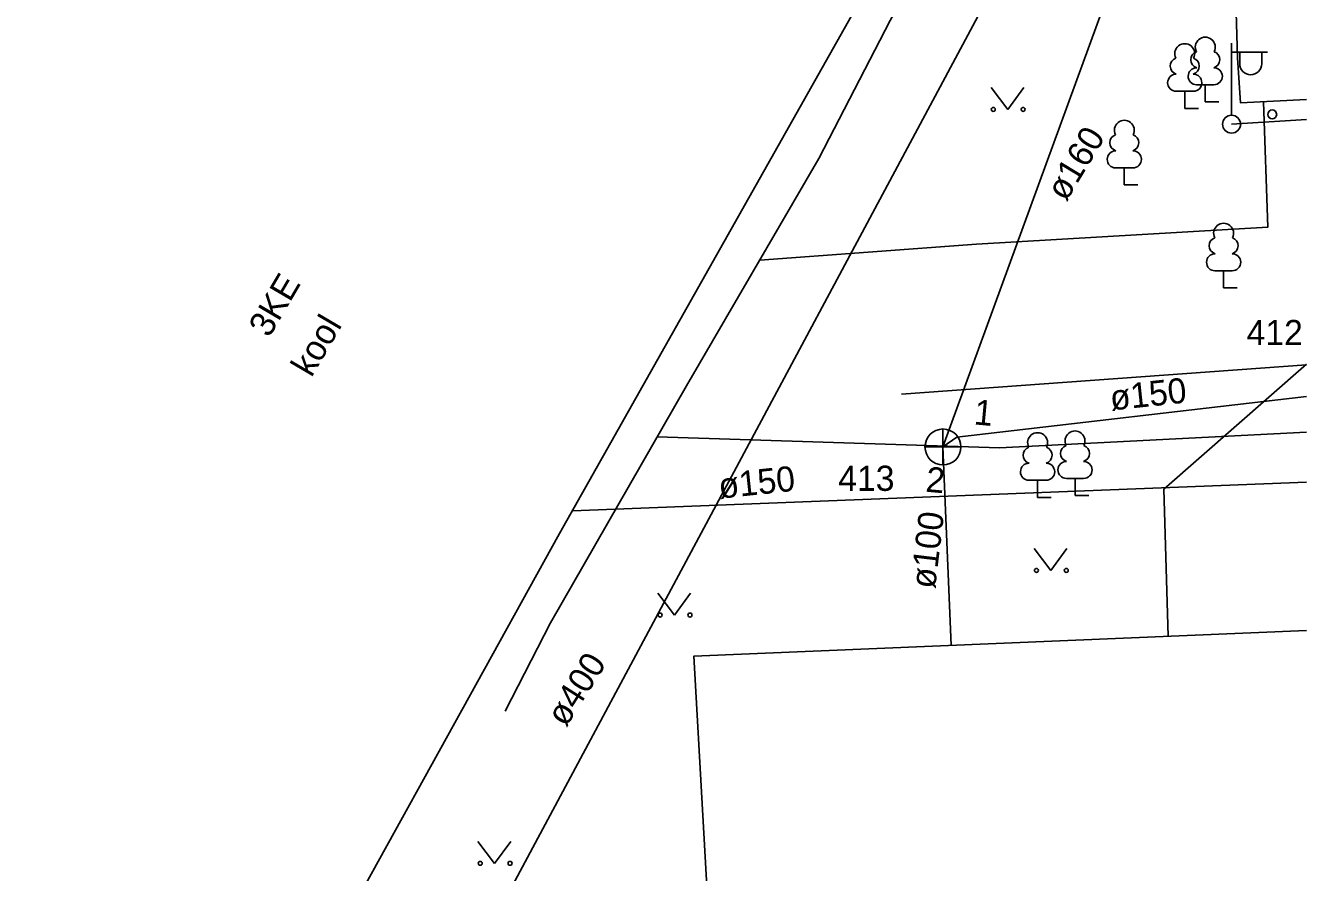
# Model space of a CAD drawing. Extents: x 713540 to 713867, y 6589774 to 6590061.
# Drawn here: x 713831.07 to 713866.67, y 6589884.71 to 6589908.24 of the extents above; entities that cross this region are included whole.
import ezdxf

# ---------------------------------------------------------------- set-up
doc = ezdxf.new("R2010")
doc.units = 0
for name, color, linetype in [('AED', 7, 'Continuous'), ('HALJASTUS', 7, 'Continuous'), ('HOONE', 7, 'Continuous'), ('HOONEDET', 7, 'Continuous'), ('KKAEV', 7, 'Continuous'), ('KORGUS', 7, 'Continuous'), ('KTRASS', 7, 'Continuous'), ('MPKAABEL', 7, 'Continuous'), ('POST', 7, 'Continuous'), ('PUU', 7, 'Continuous'), ('SIKAEV', 7, 'Continuous'), ('SKTRASS', 7, 'Continuous'), ('TEE', 7, 'Continuous'), ('TORU NR', 7, 'Continuous'), ('TTRASS', 7, 'Continuous'), ('VTRASS', 7, 'Continuous')]:
    doc.layers.add(name, color=color, linetype=linetype)

msp = doc.modelspace()

# ---------------------------------------------------------------- linework, layer by layer
at = {"layer": 'AED'}
msp.add_lwpolyline([(713866.671, 6589912.481), (713864.61, 6589912.43), (713864.76, 6589907.34)], dxfattribs=at)
at = {"layer": 'HALJASTUS'}
for p, q in [((713857.907, 6589906.517), (713858.37, 6589905.91)), ((713858.37, 6589905.91), (713858.816, 6589906.517)), ((713859.107, 6589893.707), (713859.57, 6589893.1)), ((713859.57, 6589893.1), (713860.016, 6589893.707)), ((713848.647, 6589892.467), (713849.11, 6589891.86)), ((713849.11, 6589891.86), (713849.556, 6589892.467)), ((713843.647, 6589885.567), (713844.11, 6589884.96)), ((713844.11, 6589884.96), (713844.556, 6589885.567))]:
    msp.add_line(p, q, dxfattribs=at)
for centre in [(713857.969, 6589905.91), (713858.798, 6589905.91), (713859.169, 6589893.1), (713859.998, 6589893.1), (713848.709, 6589891.86), (713849.538, 6589891.86), (713843.709, 6589884.96), (713844.538, 6589884.96)]:
    msp.add_circle(centre, 0.055, dxfattribs=at)
at = {"layer": 'HOONE'}
for points in [[(713856.15, 6589912.28), (713845.91, 6589894.13), (713837.77, 6589879.4), (713837.43, 6589878.96), (713832.83, 6589881.48), (713819.45, 6589888.61), (713819.6, 6589888.94), (713824.63, 6589897.88), (713832.94, 6589912.52), (713838.13, 6589921.78), (713838.47, 6589921.97), (713856.15, 6589912.28)], [(713866.671, 6589877.86), (713857.16, 6589877.52), (713857.19, 6589877.05), (713856.57, 6589877.02), (713856.53, 6589877.49), (713851.07, 6589877.28), (713851.1, 6589876.94), (713850.42, 6589876.94), (713849.65, 6589890.72), (713866.671, 6589891.434)]]:
    msp.add_lwpolyline(points, dxfattribs=at)
at = {"layer": 'HOONEDET'}
msp.add_lwpolyline([(713844.4, 6589889.19), (713845.66, 6589891.64), (713849.44, 6589898.23), (713853.12, 6589904.55), (713855.1, 6589908.38), (713857.62, 6589912.89), (713857.38, 6589913.08), (713854.43, 6589914.73), (713846.51, 6589918.99), (713840.16, 6589922.39), (713838.17, 6589923.4), (713838.03, 6589923.31), (713837.2, 6589921.95), (713835.31, 6589918.61), (713828.38, 6589906.13), (713826.7, 6589903.28)], dxfattribs=at)
at = {"layer": 'KKAEV'}
for p, q in [((713856.57, 6589896.03), (713856.57, 6589897.03)), ((713856.07, 6589896.53), (713857.07, 6589896.53))]:
    msp.add_line(p, q, dxfattribs=at)
msp.add_circle((713856.57, 6589896.53), 0.5, dxfattribs=at)
at = {"layer": 'KORGUS'}
msp.add_circle((713865.72, 6589905.77), 0.125, dxfattribs=at)
at = {"layer": 'KTRASS'}
for points in [[(713856.57, 6589896.53), (713861.67, 6589910.52), (713861.34, 6589915.78), (713854.21, 6589922.12)], [(713866.671, 6589897.935), (713856.96, 6589896.8), (713856.57, 6589896.53)], [(713856.57, 6589896.53), (713856.8, 6589891.02)]]:
    msp.add_lwpolyline(points, dxfattribs=at)
at = {"layer": 'MPKAABEL'}
for points in [[(713864.59, 6589905.5), (713866.671, 6589905.629)], [(713846.27, 6589894.76), (713866.671, 6589895.55)]]:
    msp.add_lwpolyline(points, dxfattribs=at)
at = {"layer": 'POST'}
for p, q in [((713864.59, 6589905.75), (713864.59, 6589907.75)), ((713864.59, 6589907.5), (713865.59, 6589907.5)), ((713864.817, 6589907.179), (713864.817, 6589907.5)), ((713865.429, 6589907.179), (713865.429, 6589907.5))]:
    msp.add_line(p, q, dxfattribs=at)
msp.add_circle((713864.59, 6589905.5), 0.25, dxfattribs=at)
msp.add_arc((713865.123, 6589907.179), 0.306, 180, 0, dxfattribs=at)
at = {"layer": 'PUU'}
for p, q in [((713863.53, 6589906.415), (713863.05, 6589906.415)), ((713863.29, 6589905.94), (713863.29, 6589906.415)), ((713864.1, 6589906.595), (713863.62, 6589906.595)), ((713863.86, 6589906.12), (713863.86, 6589906.595)), ((713864.24, 6589906.12), (713863.86, 6589906.12)), ((713863.67, 6589905.94), (713863.29, 6589905.94)), ((713861.85, 6589904.285), (713861.37, 6589904.285)), ((713861.61, 6589903.81), (713861.61, 6589904.285)), ((713861.99, 6589903.81), (713861.61, 6589903.81)), ((713864.61, 6589901.425), (713864.13, 6589901.425)), ((713864.37, 6589900.95), (713864.37, 6589901.425)), ((713864.75, 6589900.95), (713864.37, 6589900.95)), ((713859.44, 6589895.605), (713858.96, 6589895.605)), ((713859.2, 6589895.13), (713859.2, 6589895.605)), ((713860.48, 6589895.655), (713860, 6589895.655)), ((713860.24, 6589895.18), (713860.24, 6589895.655)), ((713859.58, 6589895.13), (713859.2, 6589895.13)), ((713860.62, 6589895.18), (713860.24, 6589895.18))]:
    msp.add_line(p, q, dxfattribs=at)
for centre, radius, start, end in [((713863.86, 6589907.64), 0.277, 332.5799, 207.4201), ((713863.29, 6589907.46), 0.277, 332.5799, 207.4201), ((713863.69, 6589907.293), 0.233, 109.0217, 253.1415), ((713864.03, 6589907.293), 0.233, 286.8508, 70.9859), ((713863.12, 6589907.113), 0.233, 109.0217, 253.1415), ((713863.623, 6589906.832), 0.238, 90.0016, 269.3953), ((713863.46, 6589907.113), 0.233, 286.8508, 70.9859), ((713864.097, 6589906.832), 0.238, 270.6047, 89.9984), ((713863.053, 6589906.652), 0.238, 90.0016, 269.3953), ((713863.527, 6589906.652), 0.238, 270.6047, 89.9984), ((713861.61, 6589905.33), 0.277, 332.5799, 207.4201), ((713861.44, 6589904.983), 0.233, 109.0217, 253.1415), ((713861.78, 6589904.983), 0.233, 286.8508, 70.9859), ((713861.373, 6589904.522), 0.238, 90.0016, 269.3953), ((713861.847, 6589904.522), 0.238, 270.6047, 89.9984), ((713864.37, 6589902.47), 0.277, 332.5799, 207.4201), ((713864.2, 6589902.123), 0.233, 109.0217, 253.1415), ((713864.54, 6589902.123), 0.233, 286.8508, 70.9859), ((713864.133, 6589901.662), 0.238, 90.0016, 269.3953), ((713864.607, 6589901.662), 0.238, 270.6047, 89.9984), ((713859.2, 6589896.65), 0.277, 332.5799, 207.4201), ((713860.24, 6589896.7), 0.277, 332.5799, 207.4201), ((713859.03, 6589896.303), 0.233, 109.0217, 253.1415), ((713859.37, 6589896.303), 0.233, 286.8508, 70.9859), ((713860.07, 6589896.353), 0.233, 109.0217, 253.1415), ((713860.41, 6589896.353), 0.233, 286.8508, 70.9859), ((713858.963, 6589895.842), 0.238, 90.0016, 269.3953), ((713859.437, 6589895.842), 0.238, 270.6047, 89.9984), ((713860.003, 6589895.892), 0.238, 90.0016, 269.3953), ((713860.477, 6589895.892), 0.238, 270.6047, 89.9984)]:
    msp.add_arc(centre, radius, start, end, dxfattribs=at)
at = {"layer": 'SKTRASS'}
msp.add_lwpolyline([(713837.821, 6589871.685), (713858.87, 6589910.99), (713860.1, 6589914.37), (713852.11, 6589921.91), (713866.671, 6589948.059)], dxfattribs=at)
at = {"layer": 'TEE'}
for points in [[(713866.671, 6589906.183), (713864.84, 6589906.09), (713864.76, 6589907.34)], [(713865.48, 6589906.12), (713865.6, 6589902.64), (713857.5, 6589902.17), (713851.48, 6589901.72)], [(713848.63, 6589896.81), (713858.14, 6589896.51), (713866.671, 6589896.945)]]:
    msp.add_lwpolyline(points, dxfattribs=at)
at = {"layer": 'TTRASS'}
msp.add_lwpolyline([(713866.671, 6589898.831), (713862.71, 6589895.36), (713862.83, 6589891.27)], dxfattribs=at)
at = {"layer": 'VTRASS'}
msp.add_lwpolyline([(713855.42, 6589898), (713866.671, 6589898.81)], dxfattribs=at)

# ---------------------------------------------------------------- texts
at = {"layer": 'HOONE'}
for s, p in [('3KE', (713837.84, 6589899.544)), ('kool', (713839.017, 6589898.442))]:
    msp.add_text(s, height=0.7, rotation=59.5828, dxfattribs=at).set_placement(p)
at = {"layer": 'SIKAEV'}
for s, p in [('412', (713865.01, 6589899.36)), ('413', (713853.66, 6589895.31))]:
    msp.add_text(s, height=0.7, dxfattribs=at).set_placement(p)
at = {"layer": 'TORU NR'}
for s, rotation, p in [('ø160', 58.7707, (713859.992, 6589903.324)), ('ø150', 6.0077, (713861.246, 6589897.543)), ('1', 354.7103, (713857.411, 6589897.16)), ('ø150', 6.0077, (713850.366, 6589895.093)), ('2', 354.7103, (713856.071, 6589895.29)), ('ø100', 83.1314, (713856.349, 6589892.572)), ('ø400', 57.4956, (713846.09, 6589888.72))]:
    msp.add_text(s, height=0.7, rotation=rotation, dxfattribs=at).set_placement(p)

doc.saveas('drawing.dxf')
